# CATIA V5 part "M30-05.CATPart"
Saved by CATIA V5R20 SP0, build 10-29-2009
Part number: M30-05
Revision: ANY
Definition: UNKNOWN
Nomenclature: M30-05
Source: Unknown
Bounding box of the stored display mesh (mm): x -50 to 50, y -50 to 50, z 0 to 20
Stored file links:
  C:\Users\Utente\Desktop\IO LAVORO\3D X SITO CF\X 3D SITO CF 27-09-2020\740T\740T-30\M30-05.CATPart
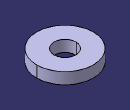
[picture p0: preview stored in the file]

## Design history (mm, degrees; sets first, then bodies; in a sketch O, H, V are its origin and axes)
Body1 "NONE" (main body)
  Solid1: solid without history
